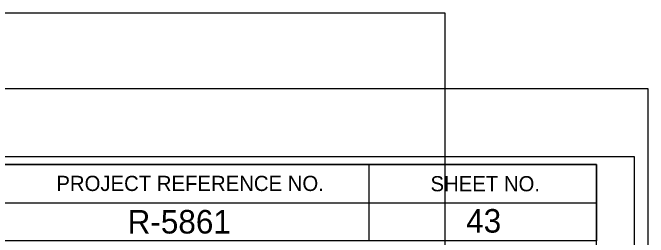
# Model space of a CAD drawing. Extents: x 505692 to 527456, y 415959 to 439886.
# Drawn here: x 507166.5 to 507375.7, y 439812.2 to 439886.1 of the extents above; entities that cross this region are included whole.
import ezdxf

# ---------------------------------------------------------------- set-up
doc = ezdxf.new("R2010")
doc.units = 0
for name, color, linetype in [('Sheet Cutting Line CELL', 7, 'Continuous'), ('Sheet Data Field CELL', 7, 'Continuous'), ('Sheet Layout Profile Border Port 1', 7, 'Continuous'), ('Sheet Plot Border Inside CELL', 7, 'Continuous'), ('Sheet Plot Border Outside CELL', 7, 'Continuous'), ('Sheet Profile CELL', 7, 'Continuous'), ('Sheet Profile Grid Major CELL', 7, 'Continuous')]:
    doc.layers.add(name, color=color, linetype=linetype)

msp = doc.modelspace()

# ---------------------------------------------------------------- linework, layer by layer
at = {"layer": 'Sheet Cutting Line CELL'}
msp.add_line((507375.68, 439861.14), (505691.68, 439861.14), dxfattribs=at)
at = {"layer": 'Sheet Layout Profile Border Port 1'}
msp.add_lwpolyline([(507058.68, 439886.14), (507308.68, 439886.14), (507308.68, 439386.14), (507058.68, 439386.14)], close=True, dxfattribs=at)
at = {"layer": 'Sheet Plot Border Inside CELL'}
msp.add_lwpolyline([(505704.68, 438783.59), (507371.18, 438783.59), (507371.18, 439838.69), (505704.68, 439838.69)], close=True, dxfattribs=at)
at = {"layer": 'Sheet Plot Border Outside CELL'}
msp.add_lwpolyline([(505691.68, 438761.14), (507375.68, 438761.14), (507375.68, 439861.14), (505691.68, 439861.14)], close=True, dxfattribs=at)
at = {"layer": 'Sheet Profile CELL'}
for p, q in [((507283.68, 439836.09), (507283.68, 439811.09)), ((507158.63, 439823.59), (507358.68, 439823.59))]:
    msp.add_line(p, q, dxfattribs=at)
for points in [[(507358.68, 439836.14), (505858.68, 439836.14), (505858.68, 438786.14), (507358.68, 438786.14)], [(507158.63, 439836.14), (507358.68, 439836.14), (507358.68, 439811.09), (507158.63, 439811.09)]]:
    msp.add_lwpolyline(points, close=True, dxfattribs=at)
at = {"layer": 'Sheet Profile Grid Major CELL'}
msp.add_lwpolyline([(507008.68, 439336.14), (507058.68, 439336.14), (507058.68, 439836.14), (507108.68, 439836.14), (507108.68, 439336.14), (507158.68, 439336.14), (507158.68, 439836.14), (507184.98, 439836.14)], dxfattribs=at)

# ---------------------------------------------------------------- texts
at = {"layer": 'Sheet Data Field CELL'}
for s, p in [('R-5861', (507204.29, 439813.46)), ('43', (507315.73, 439813.76))]:
    msp.add_text(s, height=7.75, dxfattribs=at).set_placement(p)
at = {"layer": 'Sheet Profile CELL'}
for s, height, p in [('PROJECT REFERENCE NO.', 5.0001, (507180.84, 439827.46)), ('SHEET NO.', 5, (507303.99, 439827.36))]:
    msp.add_text(s, height=height, dxfattribs=at).set_placement(p)

doc.saveas('drawing.dxf')
